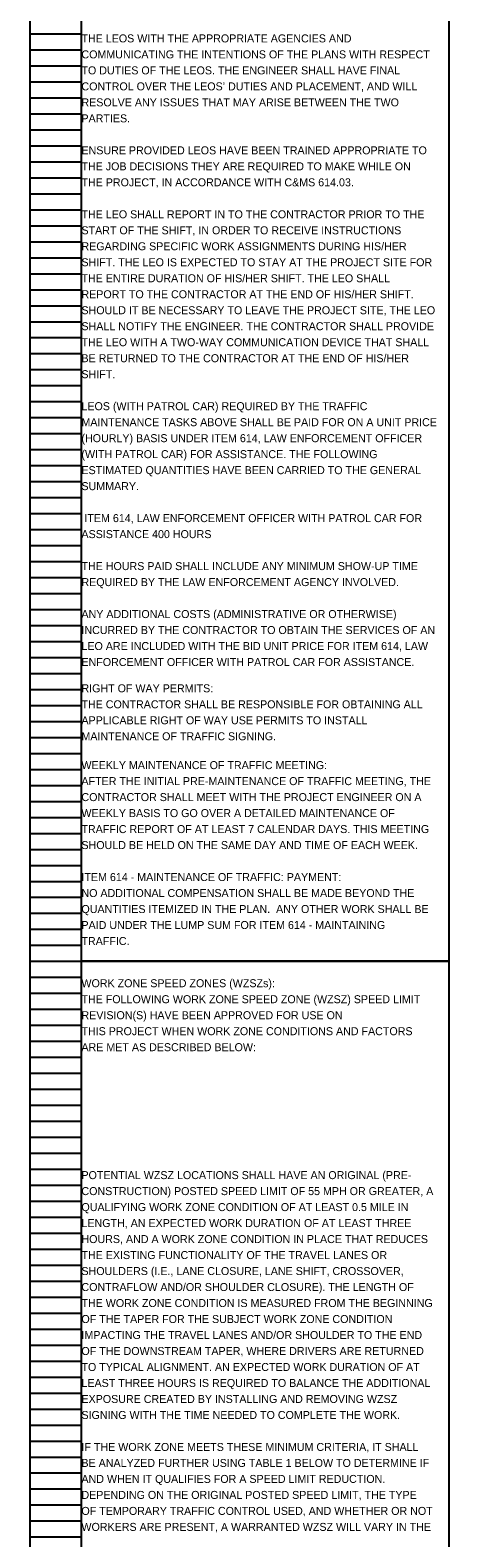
# Model space of a CAD drawing. Extents: x 16463 to 16500, y 5400 to 5823.
# Drawn here: x 16463.05 to 16470.39, y 5611.78 to 5638.18 of the extents above; entities that cross this region are included whole.
import ezdxf

# ---------------------------------------------------------------- set-up
doc = ezdxf.new("R2010")
doc.units = 0
for name, color, linetype in [('Default', 7, 'Continuous'), ('SC_Scratch1', 7, 'Continuous'), ('SH_Data', 7, 'Continuous')]:
    doc.layers.add(name, color=color, linetype=linetype)

msp = doc.modelspace()

# ---------------------------------------------------------------- linework, layer by layer
at = {"layer": 'SC_Scratch1'}
for points in [[(16463.949, 5642.032), (16470.389, 5642.032), (16470.389, 5621.872), (16463.949, 5621.872)], [(16463.949, 5621.872), (16470.389, 5621.872), (16470.389, 5601.712), (16463.949, 5601.712)]]:
    msp.add_lwpolyline(points, close=True, dxfattribs=at)
at = {"layer": 'SH_Data'}
for p, q in [((16463.049, 5621.872), (16463.049, 5642.032)), ((16463.949, 5621.872), (16463.949, 5642.032)), ((16463.049, 5638.112), (16463.949, 5638.112)), ((16463.049, 5637.832), (16463.949, 5637.832)), ((16463.049, 5637.552), (16463.949, 5637.552)), ((16463.049, 5637.272), (16463.949, 5637.272)), ((16463.049, 5636.992), (16463.949, 5636.992)), ((16463.049, 5636.712), (16463.949, 5636.712)), ((16463.049, 5636.432), (16463.949, 5636.432)), ((16463.049, 5636.152), (16463.949, 5636.152)), ((16463.049, 5635.872), (16463.949, 5635.872)), ((16463.049, 5635.592), (16463.949, 5635.592)), ((16463.049, 5635.312), (16463.949, 5635.312)), ((16463.049, 5635.032), (16463.949, 5635.032)), ((16463.049, 5634.752), (16463.949, 5634.752)), ((16463.049, 5634.472), (16463.949, 5634.472)), ((16463.049, 5634.192), (16463.949, 5634.192)), ((16463.049, 5633.912), (16463.949, 5633.912)), ((16463.049, 5633.632), (16463.949, 5633.632)), ((16463.049, 5633.352), (16463.949, 5633.352)), ((16463.049, 5633.072), (16463.949, 5633.072)), ((16463.049, 5632.792), (16463.949, 5632.792)), ((16463.049, 5632.512), (16463.949, 5632.512)), ((16463.049, 5632.232), (16463.949, 5632.232)), ((16463.049, 5631.952), (16463.949, 5631.952)), ((16463.049, 5631.672), (16463.949, 5631.672)), ((16463.049, 5631.392), (16463.949, 5631.392)), ((16463.049, 5631.112), (16463.949, 5631.112)), ((16463.049, 5630.832), (16463.949, 5630.832)), ((16463.049, 5630.552), (16463.949, 5630.552)), ((16463.049, 5630.272), (16463.949, 5630.272)), ((16463.049, 5629.992), (16463.949, 5629.992)), ((16463.049, 5629.712), (16463.949, 5629.712)), ((16463.049, 5629.432), (16463.949, 5629.432)), ((16463.049, 5629.152), (16463.949, 5629.152)), ((16463.049, 5628.872), (16463.949, 5628.872)), ((16463.049, 5628.592), (16463.949, 5628.592)), ((16463.049, 5628.312), (16463.949, 5628.312)), ((16463.049, 5628.032), (16463.949, 5628.032)), ((16463.049, 5627.752), (16463.949, 5627.752)), ((16463.049, 5627.472), (16463.949, 5627.472)), ((16463.049, 5627.192), (16463.949, 5627.192)), ((16463.049, 5626.912), (16463.949, 5626.912)), ((16463.049, 5626.632), (16463.949, 5626.632)), ((16463.049, 5626.352), (16463.949, 5626.352)), ((16463.049, 5626.072), (16463.949, 5626.072)), ((16463.049, 5625.792), (16463.949, 5625.792)), ((16463.049, 5625.512), (16463.949, 5625.512)), ((16463.049, 5625.232), (16463.949, 5625.232)), ((16463.049, 5624.952), (16463.949, 5624.952)), ((16463.049, 5624.672), (16463.949, 5624.672)), ((16463.049, 5624.392), (16463.949, 5624.392)), ((16463.049, 5624.112), (16463.949, 5624.112)), ((16463.049, 5623.832), (16463.949, 5623.832)), ((16463.049, 5623.552), (16463.949, 5623.552)), ((16463.049, 5623.272), (16463.949, 5623.272)), ((16463.049, 5622.992), (16463.949, 5622.992)), ((16463.049, 5622.712), (16463.949, 5622.712)), ((16463.049, 5622.432), (16463.949, 5622.432)), ((16463.049, 5622.152), (16463.949, 5622.152)), ((16463.049, 5601.712), (16463.049, 5621.872)), ((16463.049, 5621.872), (16463.949, 5621.872)), ((16463.049, 5621.872), (16463.949, 5621.872)), ((16463.949, 5601.712), (16463.949, 5621.872)), ((16463.049, 5621.592), (16463.949, 5621.592)), ((16463.049, 5621.312), (16463.949, 5621.312)), ((16463.049, 5621.032), (16463.949, 5621.032)), ((16463.049, 5620.752), (16463.949, 5620.752)), ((16463.049, 5620.472), (16463.949, 5620.472)), ((16463.049, 5620.192), (16463.949, 5620.192)), ((16463.049, 5619.912), (16463.949, 5619.912)), ((16463.049, 5619.632), (16463.949, 5619.632)), ((16463.049, 5619.352), (16463.949, 5619.352)), ((16463.049, 5619.072), (16463.949, 5619.072)), ((16463.049, 5618.792), (16463.949, 5618.792)), ((16463.049, 5618.512), (16463.949, 5618.512)), ((16463.049, 5618.232), (16463.949, 5618.232)), ((16463.049, 5617.952), (16463.949, 5617.952)), ((16463.049, 5617.672), (16463.949, 5617.672)), ((16463.049, 5617.392), (16463.949, 5617.392)), ((16463.049, 5617.112), (16463.949, 5617.112)), ((16463.049, 5616.832), (16463.949, 5616.832)), ((16463.049, 5616.552), (16463.949, 5616.552)), ((16463.049, 5616.272), (16463.949, 5616.272)), ((16463.049, 5615.992), (16463.949, 5615.992)), ((16463.049, 5615.712), (16463.949, 5615.712)), ((16463.049, 5615.432), (16463.949, 5615.432)), ((16463.049, 5615.152), (16463.949, 5615.152)), ((16463.049, 5614.872), (16463.949, 5614.872)), ((16463.049, 5614.592), (16463.949, 5614.592)), ((16463.049, 5614.312), (16463.949, 5614.312)), ((16463.049, 5614.032), (16463.949, 5614.032)), ((16463.049, 5613.752), (16463.949, 5613.752)), ((16463.049, 5613.472), (16463.949, 5613.472)), ((16463.049, 5613.192), (16463.949, 5613.192)), ((16463.049, 5612.912), (16463.949, 5612.912)), ((16463.049, 5612.632), (16463.949, 5612.632)), ((16463.049, 5612.352), (16463.949, 5612.352)), ((16463.049, 5612.072), (16463.949, 5612.072)), ((16463.049, 5611.792), (16463.949, 5611.792))]:
    msp.add_line(p, q, dxfattribs=at)

# ---------------------------------------------------------------- texts
at = {"layer": 'Default'}
for s, p in [('THE LEOS WITH THE APPROPRIATE AGENCIES AND ', (16463.949, 5637.962)), ('COMMUNICATING THE INTENTIONS OF THE PLANS WITH RESPECT ', (16463.949, 5637.682)), ('TO DUTIES OF THE LEOS. THE ENGINEER SHALL HAVE FINAL ', (16463.949, 5637.402)), ('CONTROL OVER THE LEOS’ DUTIES AND PLACEMENT, AND WILL ', (16463.949, 5637.122)), ('RESOLVE ANY ISSUES THAT MAY ARISE BETWEEN THE TWO ', (16463.949, 5636.842)), ('PARTIES. ', (16463.949, 5636.562)), ('ENSURE PROVIDED LEOS HAVE BEEN TRAINED APPROPRIATE TO ', (16463.949, 5636.002)), ('THE JOB DECISIONS THEY ARE REQUIRED TO MAKE WHILE ON ', (16463.949, 5635.722)), ('THE PROJECT, IN ACCORDANCE WITH C&MS 614.03. ', (16463.949, 5635.442)), ('THE LEO SHALL REPORT IN TO THE CONTRACTOR PRIOR TO THE ', (16463.949, 5634.882)), ('START OF THE SHIFT, IN ORDER TO RECEIVE INSTRUCTIONS ', (16463.949, 5634.602)), ('REGARDING SPECIFIC WORK ASSIGNMENTS DURING HIS/HER ', (16463.949, 5634.322)), ('SHIFT. THE LEO IS EXPECTED TO STAY AT THE PROJECT SITE FOR ', (16463.949, 5634.042)), ('THE ENTIRE DURATION OF HIS/HER SHIFT. THE LEO SHALL ', (16463.949, 5633.762)), ('REPORT TO THE CONTRACTOR AT THE END OF HIS/HER SHIFT. ', (16463.949, 5633.482)), ('SHOULD IT BE NECESSARY TO LEAVE THE PROJECT SITE, THE LEO ', (16463.949, 5633.202)), ('SHALL NOTIFY THE ENGINEER. THE CONTRACTOR SHALL PROVIDE ', (16463.949, 5632.922)), ('THE LEO WITH A TWO-WAY COMMUNICATION DEVICE THAT SHALL ', (16463.949, 5632.642)), ('BE RETURNED TO THE CONTRACTOR AT THE END OF HIS/HER ', (16463.949, 5632.362)), ('SHIFT.', (16463.949, 5632.082)), ('LEOS (WITH PATROL CAR) REQUIRED BY THE TRAFFIC ', (16463.949, 5631.522)), ('MAINTENANCE TASKS ABOVE SHALL BE PAID FOR ON A UNIT PRICE ', (16463.949, 5631.242)), ('(HOURLY) BASIS UNDER ITEM 614, LAW ENFORCEMENT OFFICER ', (16463.949, 5630.962)), ('(WITH PATROL CAR) FOR ASSISTANCE. THE FOLLOWING ', (16463.949, 5630.682)), ('ESTIMATED QUANTITIES HAVE BEEN CARRIED TO THE GENERAL ', (16463.949, 5630.402)), ('SUMMARY.', (16463.949, 5630.122)), (' ITEM 614, LAW ENFORCEMENT OFFICER WITH PATROL CAR FOR ', (16463.949, 5629.562)), ('ASSISTANCE 400 HOURS ', (16463.949, 5629.282)), ('THE HOURS PAID SHALL INCLUDE ANY MINIMUM SHOW-UP TIME ', (16463.949, 5628.722)), ('REQUIRED BY THE LAW ENFORCEMENT AGENCY INVOLVED. ', (16463.949, 5628.442)), ('ANY ADDITIONAL COSTS (ADMINISTRATIVE OR OTHERWISE) ', (16463.949, 5627.882)), ('INCURRED BY THE CONTRACTOR TO OBTAIN THE SERVICES OF AN ', (16463.949, 5627.602)), ('LEO ARE INCLUDED WITH THE BID UNIT PRICE FOR ITEM 614, LAW ', (16463.949, 5627.322)), ('ENFORCEMENT OFFICER WITH PATROL CAR FOR ASSISTANCE.', (16463.949, 5627.042)), ('RIGHT OF WAY PERMITS:', (16463.949, 5626.582)), ('THE CONTRACTOR SHALL BE RESPONSIBLE FOR OBTAINING ALL ', (16463.949, 5626.302)), ('APPLICABLE RIGHT OF WAY USE PERMITS TO INSTALL ', (16463.949, 5626.022)), ('MAINTENANCE OF TRAFFIC SIGNING.', (16463.949, 5625.742)), ('WEEKLY MAINTENANCE OF TRAFFIC MEETING:', (16463.949, 5625.237)), ('AFTER THE INITIAL PRE-MAINTENANCE OF TRAFFIC MEETING, THE ', (16463.949, 5624.957)), ('CONTRACTOR SHALL MEET WITH THE PROJECT ENGINEER ON A ', (16463.949, 5624.677)), ('WEEKLY BASIS TO GO OVER A DETAILED MAINTENANCE OF ', (16463.949, 5624.397)), ('TRAFFIC REPORT OF AT LEAST 7 CALENDAR DAYS. THIS MEETING ', (16463.949, 5624.117)), ('SHOULD BE HELD ON THE SAME DAY AND TIME OF EACH WEEK.', (16463.949, 5623.837)), ('ITEM 614 - MAINTENANCE OF TRAFFIC: PAYMENT:', (16463.949, 5623.277)), ('NO ADDITIONAL COMPENSATION SHALL BE MADE BEYOND THE ', (16463.949, 5622.997)), ('QUANTITIES ITEMIZED IN THE PLAN.  ANY OTHER WORK SHALL BE ', (16463.949, 5622.717)), ('PAID UNDER THE LUMP SUM FOR ITEM 614 - MAINTAINING ', (16463.949, 5622.437)), ('TRAFFIC.', (16463.949, 5622.157)), ('WORK ZONE SPEED ZONES (WZSZs):', (16463.949, 5621.418)), ('THE FOLLOWING WORK ZONE SPEED ZONE (WZSZ) SPEED LIMIT ', (16463.949, 5621.138)), ('REVISION(S) HAVE BEEN APPROVED FOR USE ON', (16463.949, 5620.858)), ('THIS PROJECT WHEN WORK ZONE CONDITIONS AND FACTORS ', (16463.949, 5620.578)), ('ARE MET AS DESCRIBED BELOW: ', (16463.949, 5620.298)), ('POTENTIAL WZSZ LOCATIONS SHALL HAVE AN ORIGINAL (PRE-', (16463.949, 5618.058)), ('CONSTRUCTION) POSTED SPEED LIMIT OF 55 MPH OR GREATER, A ', (16463.949, 5617.778)), ('QUALIFYING WORK ZONE CONDITION OF AT LEAST 0.5 MILE IN ', (16463.949, 5617.498)), ('LENGTH, AN EXPECTED WORK DURATION OF AT LEAST THREE ', (16463.949, 5617.218)), ('HOURS, AND A WORK ZONE CONDITION IN PLACE THAT REDUCES ', (16463.949, 5616.938)), ('THE EXISTING FUNCTIONALITY OF THE TRAVEL LANES OR ', (16463.949, 5616.658)), ('SHOULDERS (I.E., LANE CLOSURE, LANE SHIFT, CROSSOVER, ', (16463.949, 5616.378)), ('CONTRAFLOW AND/OR SHOULDER CLOSURE). THE LENGTH OF ', (16463.949, 5616.098)), ('THE WORK ZONE CONDITION IS MEASURED FROM THE BEGINNING ', (16463.949, 5615.818)), ('OF THE TAPER FOR THE SUBJECT WORK ZONE CONDITION ', (16463.949, 5615.538)), ('IMPACTING THE TRAVEL LANES AND/OR SHOULDER TO THE END ', (16463.949, 5615.258)), ('OF THE DOWNSTREAM TAPER, WHERE DRIVERS ARE RETURNED ', (16463.949, 5614.978)), ('TO TYPICAL ALIGNMENT. AN EXPECTED WORK DURATION OF AT ', (16463.949, 5614.698)), ('LEAST THREE HOURS IS REQUIRED TO BALANCE THE ADDITIONAL ', (16463.949, 5614.418)), ('EXPOSURE CREATED BY INSTALLING AND REMOVING WZSZ ', (16463.949, 5614.138)), ('SIGNING WITH THE TIME NEEDED TO COMPLETE THE WORK. ', (16463.949, 5613.858)), ('IF THE WORK ZONE MEETS THESE MINIMUM CRITERIA, IT SHALL ', (16463.949, 5613.298)), ('BE ANALYZED FURTHER USING TABLE 1 BELOW TO DETERMINE IF ', (16463.949, 5613.018)), ('AND WHEN IT QUALIFIES FOR A SPEED LIMIT REDUCTION. ', (16463.949, 5612.738)), ('DEPENDING ON THE ORIGINAL POSTED SPEED LIMIT, THE TYPE ', (16463.949, 5612.458)), ('OF TEMPORARY TRAFFIC CONTROL USED, AND WHETHER OR NOT ', (16463.949, 5612.178)), ('WORKERS ARE PRESENT, A WARRANTED WZSZ WILL VARY IN THE ', (16463.949, 5611.898))]:
    msp.add_text(s, height=0.14, dxfattribs=at).set_placement(p)

doc.saveas('drawing.dxf')
